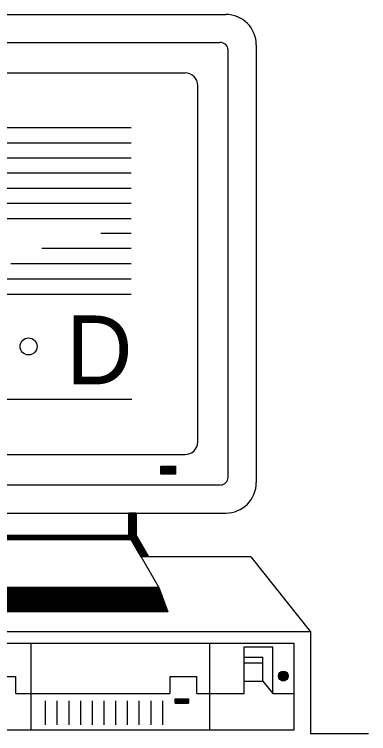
# Model space of a CAD drawing. Extents: x 22369.6 to 22389.4, y 22369.6 to 22386.
# Drawn here: x 22382.638 to 22382.893, y 22370.165 to 22370.683 of the extents above; entities that cross this region are included whole.
import ezdxf

# ---------------------------------------------------------------- set-up
doc = ezdxf.new("R2010")
doc.units = 0
for name, color, linetype in [('Level 2', 7, 'Continuous'), ('Level 25', 7, 'Continuous'), ('Level 3', 7, 'Continuous'), ('Level 5', 7, 'Continuous'), ('Level 7', 7, 'Continuous')]:
    doc.layers.add(name, color=color, linetype=linetype)

msp = doc.modelspace()

# ---------------------------------------------------------------- linework, layer by layer
at = {"layer": 'Level 2'}
for p, q in [((22382.44577, 22370.64113), (22382.76119, 22370.64113)), ((22382.77035, 22370.37534), (22382.77035, 22370.63197)), ((22382.44577, 22370.36618), (22382.76119, 22370.36618)), ((22382.74389, 22370.35755), (22382.75435, 22370.35755)), ((22382.74389, 22370.35726), (22382.75435, 22370.35726)), ((22382.74389, 22370.35693), (22382.75435, 22370.35693)), ((22382.74389, 22370.35655), (22382.75435, 22370.35655)), ((22382.74389, 22370.35622), (22382.75435, 22370.35622)), ((22382.74389, 22370.35593), (22382.75435, 22370.35593)), ((22382.74389, 22370.35559), (22382.75435, 22370.35559)), ((22382.74389, 22370.35526), (22382.75435, 22370.35526)), ((22382.74389, 22370.35493), (22382.75435, 22370.35493)), ((22382.74389, 22370.35459), (22382.75435, 22370.35459)), ((22382.74389, 22370.35426), (22382.75435, 22370.35426)), ((22382.74389, 22370.35393), (22382.75435, 22370.35393)), ((22382.74389, 22370.35363), (22382.75435, 22370.35363)), ((22382.74389, 22370.35326), (22382.75435, 22370.35326)), ((22382.74389, 22370.35293), (22382.75435, 22370.35293)), ((22382.74389, 22370.35263), (22382.75435, 22370.35263)), ((22382.74389, 22370.3523), (22382.75435, 22370.3523)), ((22382.72081, 22370.30788), (22382.72081, 22370.32405)), ((22382.7261, 22370.32393), (22382.72081, 22370.32393)), ((22382.7261, 22370.32359), (22382.72081, 22370.32359)), ((22382.7261, 22370.3233), (22382.72081, 22370.3233)), ((22382.7261, 22370.32293), (22382.72081, 22370.32293)), ((22382.7261, 22370.32259), (22382.72081, 22370.32259)), ((22382.7261, 22370.32226), (22382.72081, 22370.32226)), ((22382.7261, 22370.32197), (22382.72081, 22370.32197)), ((22382.7261, 22370.32163), (22382.72081, 22370.32163)), ((22382.7261, 22370.32126), (22382.72081, 22370.32126)), ((22382.7261, 22370.32093), (22382.72081, 22370.32093)), ((22382.7261, 22370.32063), (22382.72081, 22370.32063)), ((22382.7261, 22370.3203), (22382.72081, 22370.3203)), ((22382.7261, 22370.31997), (22382.72081, 22370.31997)), ((22382.7261, 22370.31963), (22382.72081, 22370.31963)), ((22382.7261, 22370.3193), (22382.72081, 22370.3193)), ((22382.7261, 22370.31897), (22382.72081, 22370.31897)), ((22382.7261, 22370.31863), (22382.72081, 22370.31863)), ((22382.7261, 22370.31834), (22382.72081, 22370.31834)), ((22382.7261, 22370.31797), (22382.72081, 22370.31797)), ((22382.7261, 22370.31763), (22382.72081, 22370.31763)), ((22382.7261, 22370.31734), (22382.72081, 22370.31734)), ((22382.7261, 22370.31701), (22382.72081, 22370.31701)), ((22382.7261, 22370.31668), (22382.72081, 22370.31668)), ((22382.7261, 22370.3163), (22382.72081, 22370.3163)), ((22382.7261, 22370.31601), (22382.72081, 22370.31601)), ((22382.7261, 22370.31568), (22382.72081, 22370.31568)), ((22382.7261, 22370.31534), (22382.72081, 22370.31534)), ((22382.7261, 22370.31505), (22382.72081, 22370.31505)), ((22382.7261, 22370.31468), (22382.72081, 22370.31468)), ((22382.7261, 22370.31434), (22382.72081, 22370.31434)), ((22382.7261, 22370.31401), (22382.72081, 22370.31401)), ((22382.7261, 22370.31372), (22382.72081, 22370.31372)), ((22382.7261, 22370.31338), (22382.72081, 22370.31338)), ((22382.7261, 22370.31301), (22382.72081, 22370.31301)), ((22382.7261, 22370.31268), (22382.72081, 22370.31268)), ((22382.7261, 22370.31238), (22382.72081, 22370.31238)), ((22382.7261, 22370.31205), (22382.72081, 22370.31205)), ((22382.7261, 22370.31172), (22382.72081, 22370.31172)), ((22382.7261, 22370.31138), (22382.72081, 22370.31138)), ((22382.7261, 22370.31105), (22382.72081, 22370.31105)), ((22382.7261, 22370.31072), (22382.72081, 22370.31072)), ((22382.7261, 22370.31038), (22382.72081, 22370.31038)), ((22382.7261, 22370.31009), (22382.72081, 22370.31009)), ((22382.72089, 22370.3078), (22382.60348, 22370.3078)), ((22382.7211, 22370.30747), (22382.60348, 22370.30747)), ((22382.72127, 22370.30713), (22382.60348, 22370.30713)), ((22382.72144, 22370.3068), (22382.60348, 22370.3068)), ((22382.72164, 22370.30647), (22382.60348, 22370.30647)), ((22382.72181, 22370.30613), (22382.60348, 22370.30613)), ((22382.72202, 22370.3058), (22382.60348, 22370.3058)), ((22382.72223, 22370.30551), (22382.60348, 22370.30551)), ((22382.72244, 22370.30513), (22382.60348, 22370.30513)), ((22382.7226, 22370.3048), (22382.60348, 22370.3048)), ((22382.72264, 22370.30476), (22382.60348, 22370.30476)), ((22382.7261, 22370.30972), (22382.72081, 22370.30972)), ((22382.7261, 22370.30938), (22382.72081, 22370.30938)), ((22382.7261, 22370.30909), (22382.72081, 22370.30909)), ((22382.7261, 22370.30876), (22382.72081, 22370.30876)), ((22382.7261, 22370.30843), (22382.72081, 22370.30843)), ((22382.7261, 22370.30805), (22382.72081, 22370.30805)), ((22382.72081, 22370.30788), (22382.74227, 22370.27051)), ((22382.72619, 22370.30776), (22382.72089, 22370.30776)), ((22382.72635, 22370.30743), (22382.7211, 22370.30743)), ((22382.7266, 22370.30709), (22382.72127, 22370.30709)), ((22382.72677, 22370.3068), (22382.72152, 22370.3068)), ((22382.72694, 22370.30643), (22382.72169, 22370.30643)), ((22382.72714, 22370.30609), (22382.72185, 22370.30609)), ((22382.72731, 22370.30576), (22382.72206, 22370.30576)), ((22382.72752, 22370.30547), (22382.72223, 22370.30547)), ((22382.72773, 22370.30513), (22382.72244, 22370.30513)), ((22382.72785, 22370.30476), (22382.7226, 22370.30476)), ((22382.7281, 22370.30443), (22382.72277, 22370.30443)), ((22382.72827, 22370.30413), (22382.72302, 22370.30413)), ((22382.72848, 22370.3038), (22382.72319, 22370.3038)), ((22382.72864, 22370.30347), (22382.72339, 22370.30347)), ((22382.72885, 22370.30313), (22382.72356, 22370.30313)), ((22382.72902, 22370.3028), (22382.72373, 22370.3028)), ((22382.72923, 22370.30247), (22382.72394, 22370.30247)), ((22382.72944, 22370.30213), (22382.72414, 22370.30213)), ((22382.7296, 22370.30184), (22382.72431, 22370.30184)), ((22382.72981, 22370.30147), (22382.72452, 22370.30147)), ((22382.72998, 22370.30113), (22382.72473, 22370.30113)), ((22382.73014, 22370.30084), (22382.72489, 22370.30084)), ((22382.73035, 22370.30051), (22382.72506, 22370.30051)), ((22382.73052, 22370.30018), (22382.72527, 22370.30018)), ((22382.73077, 22370.2998), (22382.72544, 22370.2998)), ((22382.73094, 22370.29951), (22382.72569, 22370.29951)), ((22382.73114, 22370.29918), (22382.72585, 22370.29918)), ((22382.73131, 22370.29884), (22382.72602, 22370.29884)), ((22382.73148, 22370.29855), (22382.72623, 22370.29855)), ((22382.73169, 22370.29818), (22382.72639, 22370.29818)), ((22382.73185, 22370.29784), (22382.7266, 22370.29784)), ((22382.73206, 22370.29751), (22382.72677, 22370.29751)), ((22382.73227, 22370.29722), (22382.72694, 22370.29722)), ((22382.73244, 22370.29688), (22382.72719, 22370.29688)), ((22382.73264, 22370.29651), (22382.72735, 22370.29651)), ((22382.73281, 22370.29618), (22382.72756, 22370.29618)), ((22382.73302, 22370.29588), (22382.72773, 22370.29588)), ((22382.73319, 22370.29555), (22382.72794, 22370.29555)), ((22382.73335, 22370.29522), (22382.7281, 22370.29522)), ((22382.7336, 22370.29488), (22382.72827, 22370.29488)), ((22382.73377, 22370.29455), (22382.72848, 22370.29455)), ((22382.73398, 22370.29422), (22382.72869, 22370.29422)), ((22382.73414, 22370.29388), (22382.72889, 22370.29388)), ((22382.73435, 22370.29359), (22382.72906, 22370.29359)), ((22382.73452, 22370.29322), (22382.72923, 22370.29322)), ((22382.73469, 22370.29288), (22382.72944, 22370.29288)), ((22382.74227, 22370.27051), (22382.60348, 22370.27051)), ((22382.74231, 22370.27038), (22382.60348, 22370.27038)), ((22382.74244, 22370.27005), (22382.60348, 22370.27005)), ((22382.7426, 22370.26976), (22382.60348, 22370.26976)), ((22382.74269, 22370.26938), (22382.60348, 22370.26938)), ((22382.74281, 22370.26905), (22382.60348, 22370.26905)), ((22382.74294, 22370.26876), (22382.60348, 22370.26876)), ((22382.74306, 22370.26843), (22382.60348, 22370.26843)), ((22382.74319, 22370.26809), (22382.60348, 22370.26809)), ((22382.74327, 22370.26772), (22382.60348, 22370.26772)), ((22382.74339, 22370.26743), (22382.60348, 22370.26743)), ((22382.74356, 22370.26709), (22382.60348, 22370.26709)), ((22382.74369, 22370.26676), (22382.60348, 22370.26676)), ((22382.74377, 22370.26647), (22382.60348, 22370.26647)), ((22382.74389, 22370.26609), (22382.60348, 22370.26609)), ((22382.74406, 22370.26576), (22382.60348, 22370.26576)), ((22382.74414, 22370.26543), (22382.60348, 22370.26543)), ((22382.74427, 22370.26513), (22382.60348, 22370.26513)), ((22382.74435, 22370.2648), (22382.60348, 22370.2648)), ((22382.74452, 22370.26443), (22382.60348, 22370.26443)), ((22382.74464, 22370.26409), (22382.60348, 22370.26409)), ((22382.74477, 22370.2638), (22382.60348, 22370.2638)), ((22382.74489, 22370.26347), (22382.60348, 22370.26347)), ((22382.74502, 22370.26313), (22382.60348, 22370.26313)), ((22382.7451, 22370.2628), (22382.60348, 22370.2628)), ((22382.74523, 22370.26247), (22382.60348, 22370.26247)), ((22382.74539, 22370.26213), (22382.60348, 22370.26213)), ((22382.74548, 22370.2618), (22382.60348, 22370.2618)), ((22382.7456, 22370.26151), (22382.60348, 22370.26151)), ((22382.74573, 22370.26113), (22382.60348, 22370.26113)), ((22382.74589, 22370.2608), (22382.60348, 22370.2608)), ((22382.74598, 22370.26051), (22382.60348, 22370.26051)), ((22382.7461, 22370.26018), (22382.60348, 22370.26018)), ((22382.74619, 22370.25984), (22382.60348, 22370.25984)), ((22382.74635, 22370.25947), (22382.60348, 22370.25947)), ((22382.74648, 22370.25918), (22382.60348, 22370.25918)), ((22382.74656, 22370.25884), (22382.60348, 22370.25884)), ((22382.74673, 22370.25851), (22382.60348, 22370.25851)), ((22382.74685, 22370.25822), (22382.60348, 22370.25822)), ((22382.74694, 22370.25784), (22382.60348, 22370.25784)), ((22382.74706, 22370.25751), (22382.60348, 22370.25751)), ((22382.74723, 22370.25718), (22382.60348, 22370.25718)), ((22382.74731, 22370.25688), (22382.60348, 22370.25688)), ((22382.74744, 22370.25655), (22382.60348, 22370.25655)), ((22382.74756, 22370.25618), (22382.60348, 22370.25618)), ((22382.74769, 22370.25584), (22382.60348, 22370.25584)), ((22382.74781, 22370.25555), (22382.60348, 22370.25555)), ((22382.74794, 22370.25522), (22382.60348, 22370.25522)), ((22382.74802, 22370.25488), (22382.60348, 22370.25488)), ((22382.74819, 22370.25455), (22382.60348, 22370.25455)), ((22382.74831, 22370.25422), (22382.60348, 22370.25422)), ((22382.74839, 22370.25388), (22382.60348, 22370.25388)), ((22382.74856, 22370.25355), (22382.60348, 22370.25355)), ((22382.74869, 22370.25326), (22382.60348, 22370.25326)), ((22382.74877, 22370.25297), (22382.60348, 22370.25297)), ((22382.65056, 22370.16759), (22382.65056, 22370.2303)), ((22382.77894, 22370.16759), (22382.77894, 22370.2303)), ((22382.80373, 22370.19397), (22382.80373, 22370.22759)), ((22382.80373, 22370.22759), (22382.82444, 22370.22759)), ((22382.82444, 22370.19397), (22382.82444, 22370.22759)), ((22382.80373, 22370.2203), (22382.8171, 22370.2203)), ((22382.8171, 22370.20284), (22382.8171, 22370.2203)), ((22382.80373, 22370.21609), (22382.8171, 22370.21609)), ((22382.61464, 22370.20634), (22382.63935, 22370.20634)), ((22382.63935, 22370.19397), (22382.63935, 22370.20634)), ((22382.75039, 22370.20634), (22382.76973, 22370.20634)), ((22382.75039, 22370.19397), (22382.75039, 22370.20634)), ((22382.76973, 22370.19397), (22382.76973, 22370.20634)), ((22382.82839, 22370.20672), (22382.83539, 22370.20672)), ((22382.82844, 22370.20709), (22382.83535, 22370.20709)), ((22382.82844, 22370.20643), (22382.83539, 22370.20643)), ((22382.82848, 22370.20743), (22382.83531, 22370.20743)), ((22382.82856, 22370.20772), (22382.83527, 22370.20772)), ((22382.82864, 22370.20805), (22382.8351, 22370.20805)), ((22382.82885, 22370.20838), (22382.83498, 22370.20838)), ((22382.82902, 22370.20876), (22382.83477, 22370.20876)), ((22382.82931, 22370.20905), (22382.83448, 22370.20905)), ((22382.8296, 22370.20938), (22382.83414, 22370.20938)), ((22382.83006, 22370.20972), (22382.83369, 22370.20972)), ((22382.83085, 22370.21001), (22382.83298, 22370.21001)), ((22382.80373, 22370.20284), (22382.8171, 22370.20284)), ((22382.8171, 22370.20284), (22382.82444, 22370.19397)), ((22382.82848, 22370.20609), (22382.83531, 22370.20609)), ((22382.82852, 22370.20576), (22382.83527, 22370.20576)), ((22382.82864, 22370.20543), (22382.8351, 22370.20543)), ((22382.82881, 22370.20509), (22382.83498, 22370.20509)), ((22382.82898, 22370.20476), (22382.83481, 22370.20476)), ((22382.82927, 22370.20443), (22382.83452, 22370.20443)), ((22382.82956, 22370.20413), (22382.83419, 22370.20413)), ((22382.83002, 22370.2038), (22382.83381, 22370.2038)), ((22382.83069, 22370.20343), (22382.8331, 22370.20343)), ((22382.63935, 22370.19397), (22382.75027, 22370.19397)), ((22382.76973, 22370.19397), (22382.80373, 22370.19397)), ((22382.82444, 22370.19397), (22382.83935, 22370.19397)), ((22382.75419, 22370.1903), (22382.7636, 22370.1903)), ((22382.75419, 22370.19001), (22382.7636, 22370.19001)), ((22382.75419, 22370.18963), (22382.7636, 22370.18963)), ((22382.75419, 22370.1893), (22382.7636, 22370.1893)), ((22382.75419, 22370.18901), (22382.7636, 22370.18901)), ((22382.75419, 22370.18868), (22382.7636, 22370.18868)), ((22382.75419, 22370.18834), (22382.7636, 22370.18834)), ((22382.75419, 22370.18797), (22382.7636, 22370.18797)), ((22382.75419, 22370.18768), (22382.7636, 22370.18768)), ((22382.75419, 22370.18734), (22382.7636, 22370.18734)), ((22382.75419, 22370.18701), (22382.7636, 22370.18701))]:
    msp.add_line(p, q, dxfattribs=at)
for points in [[(22382.74389, 22370.3578), (22382.75435, 22370.3578), (22382.75435, 22370.35201), (22382.74389, 22370.35201)], [(22382.7261, 22370.32405), (22382.7261, 22370.30788), (22382.73489, 22370.29263), (22382.7296, 22370.29263), (22382.72081, 22370.30788), (22382.72081, 22370.32405)], [(22382.72081, 22370.30788), (22382.72264, 22370.30476), (22382.60348, 22370.30476), (22382.60348, 22370.30788)], [(22382.74227, 22370.27051), (22382.74877, 22370.25297), (22382.60348, 22370.25297), (22382.60348, 22370.27051)], [(22382.36835, 22370.2303), (22382.83935, 22370.2303), (22382.83935, 22370.16759), (22382.36835, 22370.16759)], [(22382.75419, 22370.1903), (22382.7636, 22370.1903), (22382.7636, 22370.18701), (22382.75419, 22370.18701)]]:
    msp.add_lwpolyline(points, close=True, dxfattribs=at)
for centre, radius in [((22382.64867, 22370.44407), 0.0061), ((22382.83189, 22370.20671), 0.0035)]:
    msp.add_circle(centre, radius, dxfattribs=at)
for centre, start, end in [((22382.76117, 22370.63195), 0, 90), ((22382.76117, 22370.37535), 270, 0)]:
    msp.add_arc(centre, 0.00916, start, end, dxfattribs=at)
at = {"layer": 'Level 25'}
msp.add_line((22382.72081, 22370.30788), (22382.60348, 22370.30788), dxfattribs=at)
at = {"layer": 'Level 3'}
for p, q in [((22382.41648, 22370.68326), (22382.79048, 22370.68326)), ((22382.42027, 22370.66297), (22382.78631, 22370.66297)), ((22382.79219, 22370.34988), (22382.79219, 22370.65747)), ((22382.81248, 22370.34605), (22382.81248, 22370.66126)), ((22382.42027, 22370.34438), (22382.78631, 22370.34438)), ((22382.41648, 22370.32405), (22382.79048, 22370.32405))]:
    msp.add_line(p, q, dxfattribs=at)
for centre, radius, start, end in [((22382.79046, 22370.66125), 0.022, 0, 90), ((22382.78667, 22370.65745), 0.0055, 0, 93.8704), ((22382.78667, 22370.34985), 0.0055, 270, 0), ((22382.79046, 22370.34606), 0.022, 270, 0)]:
    msp.add_arc(centre, radius, start, end, dxfattribs=at)
at = {"layer": 'Level 5'}
for p, q in [((22382.48664, 22370.60168), (22382.72248, 22370.60168)), ((22382.62631, 22370.59076), (22382.72248, 22370.59076)), ((22382.62631, 22370.57988), (22382.72248, 22370.57988)), ((22382.62631, 22370.56901), (22382.72248, 22370.56901)), ((22382.62631, 22370.55809), (22382.72248, 22370.55809)), ((22382.62631, 22370.54718), (22382.72248, 22370.54718)), ((22382.48664, 22370.53626), (22382.72248, 22370.53626)), ((22382.72244, 22370.52543), (22382.70064, 22370.52543)), ((22382.72244, 22370.51451), (22382.65819, 22370.51451)), ((22382.72244, 22370.50363), (22382.63585, 22370.50363)), ((22382.48664, 22370.49272), (22382.72248, 22370.49272)), ((22382.48664, 22370.4818), (22382.72248, 22370.4818)), ((22382.48664, 22370.40618), (22382.72289, 22370.40618)), ((22382.7261, 22370.30788), (22382.7261, 22370.32405)), ((22382.7261, 22370.30788), (22382.73489, 22370.29263)), ((22382.80852, 22370.29263), (22382.7296, 22370.29263)), ((22382.80852, 22370.29263), (22382.85135, 22370.23859)), ((22382.85135, 22370.23859), (22382.60348, 22370.23859)), ((22382.85135, 22370.23859), (22382.85135, 22370.16518)), ((22382.85135, 22370.16518), (22382.89323, 22370.16518))]:
    msp.add_line(p, q, dxfattribs=at)
at = {"layer": 'Level 7'}
for p, q in [((22382.66089, 22370.17159), (22382.66089, 22370.18884)), ((22382.66931, 22370.17159), (22382.66931, 22370.18884)), ((22382.67773, 22370.17159), (22382.67773, 22370.18884)), ((22382.68614, 22370.17159), (22382.68614, 22370.18884)), ((22382.6946, 22370.17159), (22382.6946, 22370.18884)), ((22382.70302, 22370.17159), (22382.70302, 22370.18884)), ((22382.71148, 22370.17159), (22382.71148, 22370.18884)), ((22382.71989, 22370.17159), (22382.71989, 22370.18884)), ((22382.72827, 22370.17159), (22382.72827, 22370.18884)), ((22382.73673, 22370.17159), (22382.73673, 22370.18884)), ((22382.74514, 22370.17159), (22382.74514, 22370.18884))]:
    msp.add_line(p, q, dxfattribs=at)

# ---------------------------------------------------------------- texts
at = {"layer": 'Level 5'}
msp.add_text('D', height=0.04959, dxfattribs=at).set_placement((22382.67552, 22370.4168))

doc.saveas('drawing.dxf')
